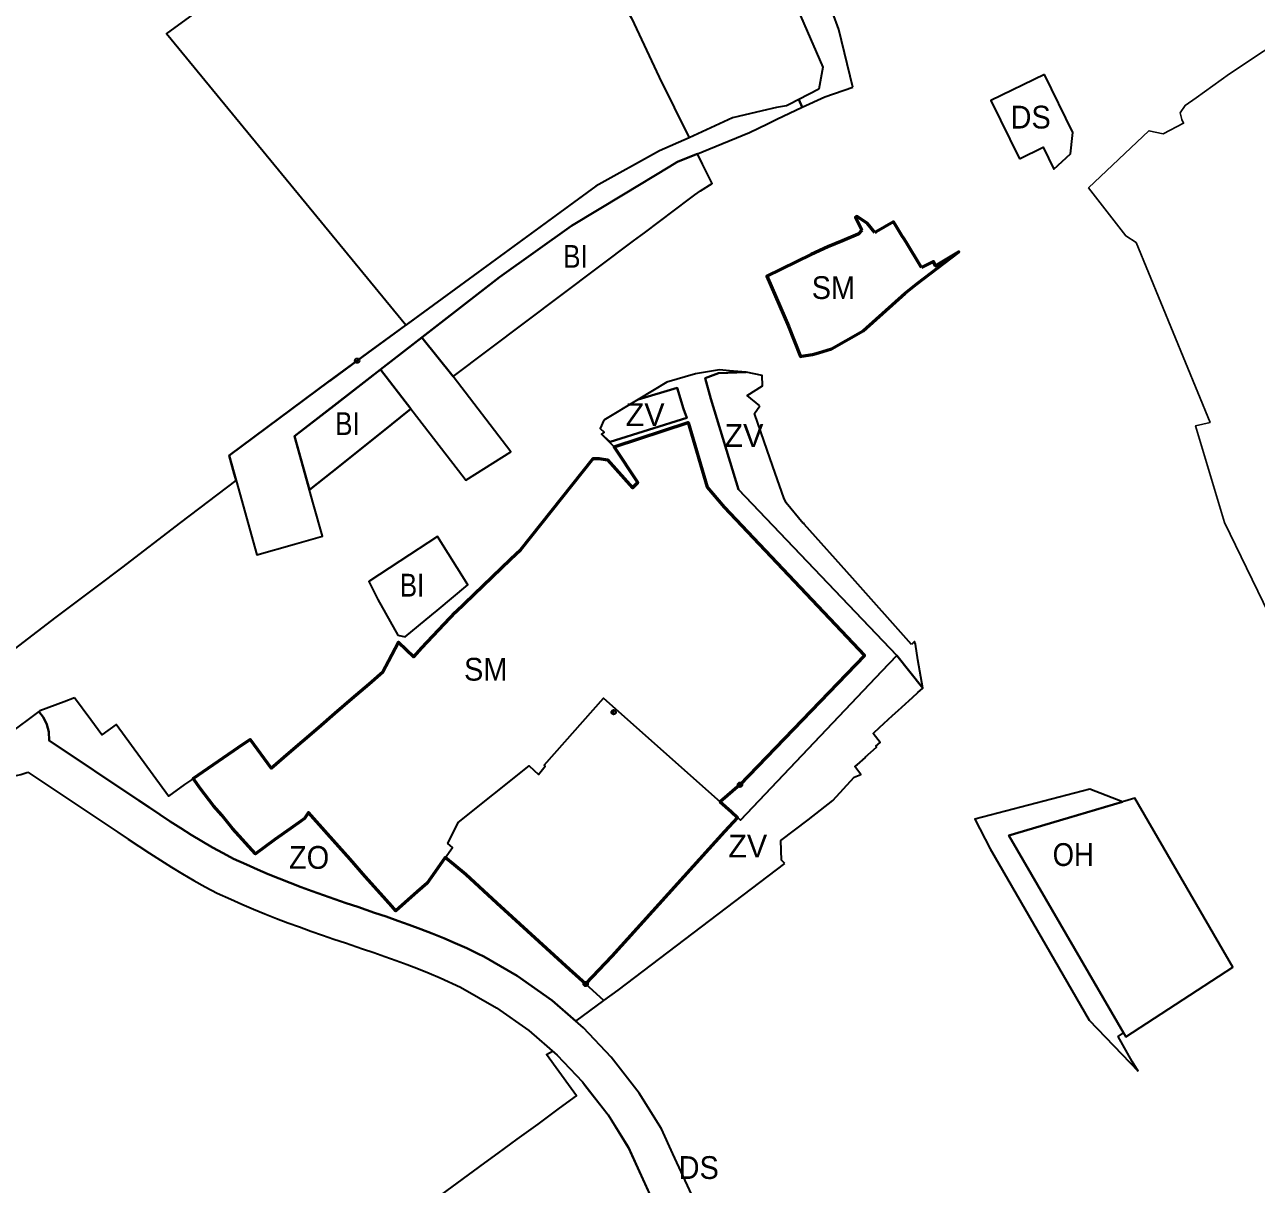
# Model space of a CAD drawing. Extents: x -650276 to -642489, y -1074311 to -1066658.
# Drawn here: x -648077 to -647428, y -1071673 to -1071063 of the extents above; entities that cross this region are included whole.
import ezdxf

# ---------------------------------------------------------------- set-up
doc = ezdxf.new("R2010")
doc.units = 0
doc.header["$LTSCALE"] = 4.8
doc.header["$PDMODE"] = 32
doc.header["$PDSIZE"] = 2.4
for name, color, linetype, lineweight in [('1', 7, 'Continuous', 35), ('10', 7, 'Continuous', 35), ('15', 7, 'Continuous', 35), ('18', 7, 'Continuous', 35), ('2', 7, 'Continuous', 35), ('24', 7, 'Continuous', 35), ('40', 7, 'Continuous', 35), ('42', 7, 'Continuous', 35), ('60', 7, 'Continuous', 53), ('61', 7, 'Continuous', 25)]:
    doc.layers.add(name, color=color, linetype=linetype, lineweight=lineweight)
doc.layers.add('62', color=7, linetype='Continuous')

msp = doc.modelspace()

# ---------------------------------------------------------------- linework, layer by layer
at = {"layer": '1'}
msp.add_lwpolyline([(-648001.922, -1071067.83), (-647977.41, -1071049.74), (-647930.7, -1071017.18), (-647911.838, -1071002.919), (-647864.03, -1070969.3), (-647864.03, -1070969.3), (-647818.33, -1070942.91), (-647810.243, -1070939.825), (-647759.52, -1071055.67), (-647757.19, -1071059.66), (-647742.64, -1071090.72), (-647726.74, -1071122.48), (-647742.35, -1071129.43), (-647775.982, -1071148.001), (-647775.982, -1071148.001), (-647875.939, -1071221.104)], close=True, dxfattribs=at)
at = {"layer": '10'}
msp.add_lwpolyline([(-647497.04, -1071595.66), (-647440.67, -1071558.93), (-647492.3, -1071470), (-647495.85, -1071471.06), (-647558.654, -1071489.738)], close=True, dxfattribs=at)
at = {"layer": '15'}
for p, q in [((-647873.25, -1071265.17), (-647845.18, -1071301.54)), ((-647708.429, -1071316.821), (-647717.363, -1071306.29))]:
    msp.add_line(p, q, dxfattribs=at)
for points in [[(-647640.727, -1071095.819), (-647648.106, -1071065.551), (-647654.747, -1071047.095), (-647657.699, -1071038.232), (-647659.01, -1071032.66)], [(-647676.96, -1071039.014), (-647676.9, -1071039.03), (-647676.45, -1071039.22), (-647656.443, -1071085.369), (-647658.55, -1071097.02), (-647669.02, -1071102.33), (-647667.35, -1071106.38), (-647655.47, -1071100.98), (-647640.727, -1071095.819)], [(-647845.18, -1071301.54), (-647844.296, -1071302.757), (-647820.698, -1071287.83), (-647850.956, -1071248.208), (-647867.586, -1071227.694), (-647889.22, -1071244.48), (-647873.25, -1071265.17)], [(-647498.271, -1071593.544), (-647558.654, -1071489.738), (-647498.8, -1071471.94), (-647515.87, -1071465.25), (-647576.471, -1071481.091), (-647568.35, -1071496.656), (-647516.376, -1071586.89), (-647490.561, -1071613.609)], [(-647490.561, -1071613.609), (-647493.6, -1071608.5), (-647501.11, -1071595.45), (-647498.271, -1071593.544)]]:
    msp.add_lwpolyline(points, dxfattribs=at)
for points in [[(-647826.56, -1071195.86), (-647788.66, -1071168.8), (-647761.366, -1071152.304), (-647737.027, -1071137.593), (-647733.38, -1071135.37), (-647732.58, -1071135.04), (-647722.51, -1071130.93), (-647716.51, -1071128.48), (-647695.08, -1071119.72), (-647685.55, -1071115.14), (-647684.15, -1071114.47), (-647680.64, -1071112.77), (-647667.35, -1071106.38), (-647669.02, -1071102.33), (-647674.17, -1071104.97), (-647675.64, -1071105.71), (-647680.82, -1071106.54), (-647688.45, -1071108.38), (-647701.04, -1071111.41), (-647703.96, -1071112.11), (-647726.74, -1071122.48), (-647742.35, -1071129.43), (-647775.982, -1071148.001), (-647895.959, -1071235.746), (-647916.161, -1071250.628), (-647916.208, -1071250.662), (-647968.896, -1071289.779), (-647965.26, -1071302.86), (-647954.38, -1071342), (-647934.51, -1071336.37), (-647919.88, -1071332.23), (-647924.53, -1071315.55), (-647934.6, -1071279.45), (-647915.6, -1071264.95), (-647889.22, -1071244.48)], [(-647625.428, -1071403.267), (-647617.49, -1071394.901), (-647700.816, -1071307.512), (-647715.355, -1071259.885), (-647718.342, -1071248.972), (-647711.447, -1071246.332), (-647696.81, -1071245.79), (-647705.59, -1071245.08), (-647710.94, -1071244.65), (-647723.57, -1071246.66), (-647738.56, -1071251.13), (-647753.647, -1071260.178), (-647733.15, -1071254.081), (-647729.795, -1071265.066), (-647728.006, -1071269.975), (-647768.445, -1071282.6), (-647772.97, -1071278.43), (-647772.07, -1071279.33), (-647766.35, -1071285.11), (-647727.368, -1071272.362), (-647717.363, -1071306.29), (-647708.429, -1071316.821), (-647634.524, -1071394.901), (-647700.078, -1071462.96), (-647710.546, -1071472.023), (-647699.767, -1071481.617)]]:
    msp.add_lwpolyline(points, close=True, dxfattribs=at)
for p in [(-647766.557, -1071424.793), (-647700.078, -1071462.96)]:
    msp.add_point(p, dxfattribs=at)
at = {"layer": '18'}
for points in [[(-647629.09, -1071172.4), (-647632.93, -1071167.71), (-647638.46, -1071163.89), (-647639.32, -1071164.22), (-647635.93, -1071171.22)], [(-647612.695, -1071177.542), (-647613.91, -1071175.57), (-647614.732, -1071174.222), (-647618.446, -1071168.166), (-647618.469, -1071168.129), (-647618.77, -1071167.64), (-647619.264, -1071166.832), (-647619.34, -1071166.709), (-647628.39, -1071172.05), (-647629.09, -1071172.4)], [(-647635.93, -1071171.22), (-647637.87, -1071173.29), (-647646.09, -1071176.68), (-647653.85, -1071179.87), (-647662.634, -1071183.968)], [(-647604.576, -1071190.781), (-647604.888, -1071190.272), (-647612.695, -1071177.542)], [(-647662.634, -1071183.968), (-647686.01, -1071195.35), (-647686.01, -1071195.35)], [(-647674.6, -1071221.71), (-647668.226, -1071237.571), (-647667.77, -1071237.5), (-647661.99, -1071236.62), (-647658.78, -1071235.63), (-647651.93, -1071233.57), (-647635.17, -1071224.18), (-647613.09, -1071204.33), (-647607.02, -1071199.34), (-647584.92, -1071182.54), (-647597.164, -1071189.857), (-647598.215, -1071187.608), (-647604.576, -1071190.781)], [(-647686.01, -1071195.35), (-647686.01, -1071195.35), (-647674.6, -1071221.71)]]:
    msp.add_lwpolyline(points, dxfattribs=at)
msp.add_lwpolyline([(-647974.66, -1071450.62), (-647977.28, -1071452.43), (-647979.88, -1071454.22), (-647982.46, -1071456), (-647985.06, -1071457.79), (-647987.8, -1071459.68), (-647984.07, -1071465.1), (-647977.13, -1071474.05), (-647972.76, -1071479), (-647967.13, -1071486.01), (-647957.07, -1071497.13), (-647955.14, -1071499.23), (-647950.56, -1071495.85), (-647944.81, -1071491.78), (-647939.31, -1071487.88), (-647933.88, -1071484.04), (-647931.17, -1071482.12), (-647929.26, -1071480.77), (-647927.2, -1071477.54), (-647919.22, -1071486.5), (-647881.16, -1071529.25), (-647876.27, -1071524.96), (-647864.69, -1071514.65), (-647851.45, -1071495.96), (-647853.77, -1071493.78), (-647848.4, -1071482.78), (-647810.97, -1071452.92), (-647806.15, -1071457.48), (-647802.53, -1071453.19), (-647803.1, -1071452.66), (-647771.82, -1071417.42), (-647710.546, -1071472.023), (-647700.078, -1071462.96), (-647634.524, -1071394.901), (-647708.429, -1071316.821), (-647717.363, -1071306.29), (-647727.368, -1071272.362), (-647766.35, -1071285.11), (-647753.89, -1071303.94), (-647756.67, -1071306.77), (-647769.85, -1071291.91), (-647774.14, -1071291.34), (-647777.4, -1071291.32), (-647815.95, -1071339.71), (-647820.93, -1071344.25), (-647849.86, -1071372.18), (-647867.45, -1071390.95), (-647871.68, -1071395.59), (-647879.76, -1071387.96), (-647885.05, -1071397.88), (-647888.11, -1071403.61), (-647895.29, -1071409.81), (-647904.3, -1071417.58), (-647911.04, -1071423.39), (-647913.31, -1071425.35), (-647921.96, -1071432.81), (-647946.78, -1071454.23), (-647957.906, -1071439.06)], close=True, dxfattribs=at)
at = {"layer": '2'}
for points in [[(-648091.92, -1071399.07), (-648060.01, -1071374.69), (-648038.18, -1071358.51), (-648025.39, -1071348.76), (-647994.31, -1071325.03), (-647965.26, -1071302.86), (-647966.226, -1071299.385), (-647968.896, -1071289.779), (-647916.208, -1071250.662), (-647895.959, -1071235.746), (-647875.939, -1071221.104), (-648001.922, -1071067.83), (-647977.41, -1071049.74)], [(-647889.22, -1071244.48), (-647915.6, -1071264.95), (-647934.6, -1071279.45), (-647926.689, -1071307.809), (-647910.73, -1071295.08)], [(-647910.73, -1071295.08), (-647907.92, -1071292.84), (-647888.77, -1071277.56), (-647873.25, -1071265.17), (-647889.22, -1071244.48)]]:
    msp.add_lwpolyline(points, dxfattribs=at)
for points in [[(-647756.03, -1071176.76), (-647750.34, -1071172.5), (-647726.56, -1071154.68), (-647723.79, -1071152.61), (-647720.85, -1071150.41), (-647714.71, -1071146.51), (-647719.73, -1071136.48), (-647722.51, -1071130.93), (-647732.58, -1071135.04), (-647733.38, -1071135.37), (-647737.027, -1071137.593), (-647761.366, -1071152.304), (-647788.66, -1071168.8), (-647826.56, -1071195.86), (-647867.586, -1071227.694), (-647850.956, -1071248.208)], [(-647926.69, -1071307.81), (-647934.6, -1071279.45), (-647889.22, -1071244.48), (-647873.25, -1071265.17), (-647888.77, -1071277.56), (-647907.92, -1071292.84), (-647910.73, -1071295.08)], [(-647879.09, -1071345.3), (-647895.37, -1071355.96), (-647890.7, -1071365.52), (-647880.14, -1071384.32), (-647876.34, -1071385.2), (-647862.25, -1071373.55), (-647859.44, -1071371.23), (-647843.23, -1071357.82), (-647859.31, -1071332.34)]]:
    msp.add_lwpolyline(points, close=True, dxfattribs=at)
msp.add_point((-647901.523, -1071239.822), dxfattribs=at)
at = {"layer": '24'}
for points in [[(-647539.818, -1071089.2), (-647568.01, -1071102.98), (-647553.01, -1071133.68)], [(-647525.1, -1071121.25), (-647524.95, -1071119.68), (-647539.817, -1071089.199)], [(-647553.01, -1071133.68), (-647540.48, -1071127.55), (-647534.851, -1071139.015), (-647526.04, -1071130.94), (-647525.1, -1071121.25)], [(-648063.593, -1071439.723), (-648063.862, -1071435.078), (-648064.838, -1071431.28), (-648066.623, -1071427.592), (-648069.022, -1071424.443), (-648101.203, -1071448.31)], [(-647834.953, -1071553.406), (-647837.929, -1071551.872), (-647843.891, -1071549), (-647849.898, -1071546.282), (-647855.937, -1071543.707), (-647861.998, -1071541.254), (-647868.073, -1071538.911), (-647874.155, -1071536.658), (-647880.233, -1071534.48), (-647886.305, -1071532.36), (-647892.363, -1071530.282), (-647901.28, -1071527.249), (-647907.294, -1071525.204), (-647913.282, -1071523.152), (-647919.238, -1071521.081), (-647925.157, -1071518.976), (-647931.035, -1071516.824), (-647936.866, -1071514.613), (-647942.644, -1071512.329), (-647948.363, -1071509.96), (-647954.016, -1071507.496), (-647959.792, -1071504.833), (-647966.547, -1071501.883), (-647972.035, -1071499.009), (-647977.67, -1071495.885), (-647983.266, -1071492.628), (-647988.829, -1071489.259), (-647994.366, -1071485.79), (-647999.887, -1071482.241), (-648005.399, -1071478.627), (-648010.917, -1071474.963), (-648016.446, -1071471.268), (-648063.593, -1071439.723)], [(-648101.203, -1071448.31), (-648098.259, -1071452.196), (-648096.014, -1071454.192), (-648093.059, -1071456.066), (-648089.539, -1071457.489), (-648085.585, -1071458.248), (-648081.642, -1071458.215), (-648078.539, -1071457.636), (-648074.86, -1071456.248)], [(-648074.86, -1071456.248), (-648027.562, -1071487.894), (-648022.005, -1071491.607), (-648016.415, -1071495.321), (-648010.777, -1071499.017), (-648005.082, -1071502.678), (-647999.319, -1071506.287), (-647993.478, -1071509.826), (-647987.55, -1071513.275), (-647981.525, -1071516.615), (-647975.201, -1071519.929), (-647967.982, -1071523.081), (-647962.2, -1071525.746), (-647956.187, -1071528.368), (-647950.146, -1071530.869), (-647944.088, -1071533.263), (-647938.019, -1071535.566), (-647931.945, -1071537.788), (-647925.874, -1071539.949), (-647919.808, -1071542.058), (-647913.756, -1071544.132), (-647907.72, -1071546.185), (-647898.827, -1071549.208), (-647892.847, -1071551.26), (-647886.903, -1071553.336), (-647881.001, -1071555.45), (-647875.147, -1071557.619), (-647869.348, -1071559.856), (-647863.611, -1071562.177), (-647857.944, -1071564.594), (-647847.103, -1071569.497)], [(-647725.629, -1071678.373), (-647735.352, -1071657.117), (-647741.34, -1071644.028), (-647753.065, -1071625.201), (-647767.784, -1071606.225), (-647782.408, -1071590.847), (-647798.911, -1071576.526), (-647817.375, -1071563.458), (-647834.953, -1071553.406)], [(-647847.103, -1071569.497), (-647828.141, -1071580.34), (-647811.272, -1071592.28), (-647796.24, -1071605.324), (-647782.97, -1071619.278)], [(-647782.97, -1071619.278), (-647769.498, -1071636.647), (-647758.994, -1071653.513), (-647743.48, -1071687.426), (-647611.514, -1071974.086)]]:
    msp.add_lwpolyline(points, dxfattribs=at)
at = {"layer": '40'}
msp.add_line((-647617.49, -1071394.901), (-647603.9, -1071412.1), dxfattribs=at)
for points in [[(-647696.81, -1071245.79), (-647711.447, -1071246.332), (-647718.342, -1071248.972), (-647715.355, -1071259.885), (-647700.816, -1071307.512), (-647617.49, -1071394.901)], [(-647689.61, -1071263.51), (-647696.35, -1071258.14), (-647688.17, -1071253.06), (-647688.46, -1071247.65), (-647696.81, -1071245.79)], [(-647728.006, -1071269.975), (-647729.795, -1071265.066), (-647733.15, -1071254.081), (-647753.647, -1071260.178), (-647771.76, -1071271.04)], [(-647666.78, -1071325.52), (-647675.85, -1071314.62), (-647677, -1071312.01), (-647681.53, -1071299.02), (-647685.74, -1071286.93), (-647692.45, -1071267.67), (-647689.61, -1071263.51)], [(-647771.76, -1071271.04), (-647773.6, -1071275.43), (-647771.59, -1071277.36), (-647772.97, -1071278.43), (-647768.445, -1071282.6), (-647728.006, -1071269.975)], [(-647609.85, -1071389.21), (-647640.92, -1071354.21), (-647666.21, -1071325.89), (-647666.629, -1071325.351), (-647666.78, -1071325.52)], [(-647603.9, -1071412.1), (-647606.39, -1071397.21), (-647607.77, -1071388.91), (-647608.31, -1071387.63), (-647609.85, -1071389.21)], [(-647617.49, -1071394.901), (-647625.428, -1071403.267), (-647699.767, -1071481.617), (-647701.415, -1071480.15)], [(-647676.51, -1071504.34), (-647678.3, -1071502.55), (-647678.56, -1071492.25), (-647664.16, -1071481.45), (-647651.2, -1071471.24), (-647640.04, -1071458.97), (-647636.48, -1071457.52), (-647639.64, -1071453.33), (-647639.11, -1071452.78), (-647638.4, -1071452.55), (-647634.04, -1071448.58), (-647634.12, -1071448.49), (-647631.16, -1071445.79), (-647628.21, -1071443.09), (-647628.55, -1071442.72), (-647626.34, -1071440.73), (-647630.04, -1071435.97), (-647629.6, -1071435.56), (-647626.65, -1071432.87), (-647619.75, -1071426.57), (-647616.75, -1071423.83), (-647611.12, -1071418.69), (-647609.25, -1071416.99), (-647606.48, -1071414.46), (-647603.9, -1071412.1), (-647617.49, -1071394.901)], [(-647701.415, -1071480.15), (-647708.18, -1071487.57), (-647767.575, -1071553.083), (-647781.31, -1071567.79), (-647771.717, -1071576.551)], [(-647771.717, -1071576.551), (-647764.23, -1071571.01), (-647676.51, -1071504.34)]]:
    msp.add_lwpolyline(points, dxfattribs=at)
at = {"layer": '42'}
for p, q in [((-647984.07, -1071465.1), (-647987.8, -1071459.68)), ((-647849.898, -1071546.282), (-647843.891, -1071549))]:
    msp.add_line(p, q, dxfattribs=at)
for points in [[(-648050.25, -1071417.19), (-648055.717, -1071419.253), (-648068.56, -1071424.1), (-648069.022, -1071424.443)], [(-647987.8, -1071459.68), (-647988.713, -1071460.33), (-647992.408, -1071462.858), (-648000.91, -1071469.01), (-648028.31, -1071431.32), (-648035.87, -1071436.62), (-648041.726, -1071428.707), (-648050.25, -1071417.19)], [(-648069.022, -1071424.443), (-648066.623, -1071427.592), (-648064.838, -1071431.28), (-648063.862, -1071435.078), (-648063.593, -1071439.723), (-648016.446, -1071471.268), (-648010.917, -1071474.963), (-648005.399, -1071478.627), (-647999.887, -1071482.241), (-647994.366, -1071485.79)], [(-647944.81, -1071491.78), (-647950.56, -1071495.85), (-647955.14, -1071499.23), (-647957.07, -1071497.13), (-647967.13, -1071486.01), (-647972.76, -1071479), (-647977.13, -1071474.05)], [(-647927.2, -1071477.54), (-647927.2, -1071477.54), (-647929.26, -1071480.77), (-647931.17, -1071482.12), (-647933.88, -1071484.04), (-647939.31, -1071487.88), (-647944.81, -1071491.78)], [(-647855.23, -1071501.297), (-647864.69, -1071514.65), (-647876.27, -1071524.96), (-647881.16, -1071529.25), (-647919.22, -1071486.5), (-647927.2, -1071477.54)], [(-647994.366, -1071485.79), (-647988.829, -1071489.259), (-647983.266, -1071492.628)], [(-647983.266, -1071492.628), (-647977.67, -1071495.885), (-647972.035, -1071499.009), (-647966.547, -1071501.883), (-647959.792, -1071504.833)], [(-647959.792, -1071504.833), (-647954.016, -1071507.496), (-647948.363, -1071509.96)], [(-647828.024, -1071525.256), (-647844.4, -1071510.2), (-647850.55, -1071505.14), (-647855.23, -1071501.297)], [(-647948.363, -1071509.96), (-647942.644, -1071512.329), (-647936.866, -1071514.613)], [(-647781.31, -1071567.79), (-647789.73, -1071560.1), (-647844.4, -1071510.2), (-647828.024, -1071525.256)], [(-647936.866, -1071514.613), (-647931.035, -1071516.824), (-647925.157, -1071518.976), (-647919.238, -1071521.081), (-647913.282, -1071523.152)], [(-647913.282, -1071523.152), (-647907.294, -1071525.204), (-647901.28, -1071527.249)], [(-647901.28, -1071527.249), (-647892.363, -1071530.282), (-647886.305, -1071532.36), (-647880.233, -1071534.48), (-647874.155, -1071536.658), (-647868.073, -1071538.911), (-647861.998, -1071541.254), (-647855.937, -1071543.707), (-647849.898, -1071546.282)], [(-647843.891, -1071549), (-647837.929, -1071551.872), (-647834.953, -1071553.406)], [(-647834.953, -1071553.406), (-647817.375, -1071563.458), (-647798.911, -1071576.526), (-647786.379, -1071587.401), (-647771.717, -1071576.551), (-647781.31, -1071567.79)], [(-647857.52, -1071678.92), (-647834.345, -1071661.969), (-647827.42, -1071656.89), (-647817.33, -1071649.51), (-647806.35, -1071641.47), (-647795.76, -1071633.72), (-647794.98, -1071633.15), (-647786.1, -1071626.65), (-647788.942, -1071622.735), (-647801.84, -1071604.97), (-647798.8, -1071603.102), (-647796.24, -1071605.324), (-647782.97, -1071619.278), (-647781.134, -1071621.645), (-647769.498, -1071636.647), (-647758.889, -1071653.742), (-647743.48, -1071687.426)]]:
    msp.add_lwpolyline(points, dxfattribs=at)
msp.add_point((-647781.31, -1071567.79), dxfattribs=at)
at = {"layer": '60'}
for points in [[(-647629.09, -1071172.4), (-647632.93, -1071167.71), (-647638.46, -1071163.89), (-647639.32, -1071164.22), (-647635.93, -1071171.22)], [(-647612.695, -1071177.542), (-647613.91, -1071175.57), (-647614.732, -1071174.222), (-647618.446, -1071168.166), (-647618.469, -1071168.129), (-647618.77, -1071167.64), (-647619.264, -1071166.832), (-647619.34, -1071166.709), (-647628.39, -1071172.05), (-647629.09, -1071172.4)], [(-647635.93, -1071171.22), (-647637.87, -1071173.29), (-647646.09, -1071176.68), (-647653.85, -1071179.87), (-647662.634, -1071183.968)], [(-647604.576, -1071190.781), (-647604.888, -1071190.272), (-647612.695, -1071177.542)], [(-647662.634, -1071183.968), (-647686.01, -1071195.35), (-647686.01, -1071195.35)], [(-647674.6, -1071221.71), (-647668.226, -1071237.571), (-647667.77, -1071237.5), (-647661.99, -1071236.62), (-647658.78, -1071235.63), (-647651.93, -1071233.57), (-647635.17, -1071224.18), (-647613.09, -1071204.33), (-647607.02, -1071199.34), (-647584.92, -1071182.54), (-647597.164, -1071189.857), (-647598.215, -1071187.608), (-647604.576, -1071190.781)], [(-647686.01, -1071195.35), (-647686.01, -1071195.35), (-647674.6, -1071221.71)]]:
    msp.add_lwpolyline(points, dxfattribs=at)
msp.add_lwpolyline([(-647777.4, -1071291.32), (-647777.4, -1071291.32), (-647774.14, -1071291.34), (-647769.85, -1071291.91), (-647756.67, -1071306.77), (-647753.89, -1071303.94), (-647766.35, -1071285.11), (-647727.368, -1071272.362), (-647717.363, -1071306.29), (-647708.429, -1071316.821), (-647634.524, -1071394.901), (-647700.078, -1071462.96), (-647710.546, -1071472.023), (-647704.78, -1071477.1), (-647701.415, -1071480.15), (-647708.18, -1071487.57), (-647767.575, -1071553.083), (-647781.31, -1071567.79), (-647789.73, -1071560.1), (-647828.024, -1071525.256), (-647844.4, -1071510.2), (-647850.55, -1071505.14), (-647855.23, -1071501.297), (-647860.576, -1071508.843), (-647864.69, -1071514.65), (-647869.922, -1071519.269), (-647876.29, -1071524.89), (-647881.16, -1071529.25), (-647883.31, -1071526.83), (-647889.29, -1071520.11), (-647897.27, -1071511.15), (-647905.25, -1071502.19), (-647917.23, -1071488.75), (-647927.2, -1071477.54), (-647929.26, -1071480.77), (-647931.17, -1071482.12), (-647936.59, -1071485.96), (-647944.81, -1071491.78), (-647955.14, -1071499.23), (-647967.13, -1071486.01), (-647972.76, -1071479), (-647977.13, -1071474.05), (-647984.07, -1071465.1), (-647987.8, -1071459.68), (-647961.4, -1071441.47), (-647957.906, -1071439.06), (-647946.78, -1071454.23), (-647937.43, -1071446.16), (-647930.38, -1071440.08), (-647921.96, -1071432.81), (-647913.31, -1071425.35), (-647904.3, -1071417.58), (-647895.29, -1071409.81), (-647888.11, -1071403.61), (-647885.05, -1071397.88), (-647879.76, -1071387.96), (-647871.68, -1071395.59), (-647867.45, -1071390.95), (-647849.86, -1071372.18), (-647820.93, -1071344.25), (-647815.474, -1071339.22)], close=True, dxfattribs=at)
at = {"layer": '61'}
msp.add_lwpolyline([(-647415.97, -1071385.01), (-647445, -1071324.99), (-647460.28, -1071274.02), (-647452.69, -1071272.32), (-647491.56, -1071177.65), (-647497.03, -1071174.18), (-647516.65, -1071148.87), (-647484.84, -1071118.8), (-647477.3, -1071120.38), (-647466.6, -1071114.88), (-647467.47, -1071112.93), (-647468.47, -1071109.42), (-647465.83, -1071105.54), (-647460.06, -1071101.57), (-647442.36, -1071088.82), (-647406.52, -1071065.05)], dxfattribs=at)

# ---------------------------------------------------------------- texts
at = {"layer": '62'}
for s, width, p in [('DS', 0.95, (-647557.693, -1071117.661)), ('BI', 0.85, (-647793.1, -1071190.942)), ('SM', 0.95, (-647662.328, -1071207.374)), ('BI', 0.85, (-647913.1, -1071278.942)), ('BI', 0.85, (-647879.1, -1071363.942)), ('SM', 0.95, (-647845.307, -1071408.18)), ('ZO', 0.95, (-647937.423, -1071507.188)), ('OH', 0.9, (-647535.508, -1071505.684)), ('DS', 0.95, (-647732.378, -1071670.379))]:
    msp.add_text(s, height=12, dxfattribs=dict(at, width=width)).set_placement(p)
for p in [(-647760.241, -1071274.214), (-647708.241, -1071285.214), (-647706.241, -1071501.214)]:
    msp.add_text('ZV', height=12, dxfattribs=at).set_placement(p)

doc.saveas('drawing.dxf')
